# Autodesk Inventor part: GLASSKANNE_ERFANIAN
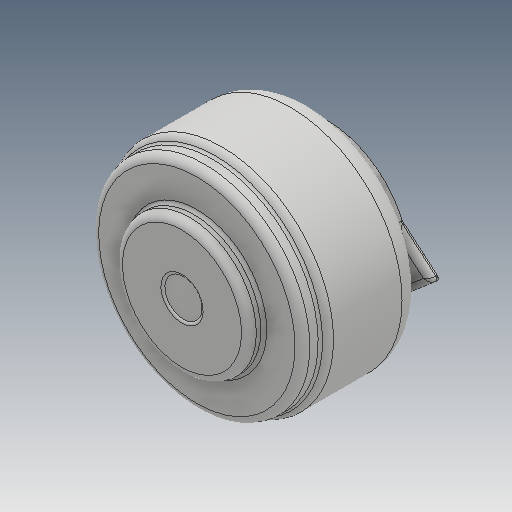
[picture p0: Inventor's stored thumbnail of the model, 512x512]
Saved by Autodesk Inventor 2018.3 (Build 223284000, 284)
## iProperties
Created: 2019-01
Part Number: GLASSKANNE_ERFANIAN
Material: Generisch
Document SubType Name: Modeling
Designer: zand
Density: 1 g/cm^3
Appearance: Vorgabe
Mass: 310.714 g
Surface Area: 1163.89 cm^2
Volume: 310.714 cm^3
Author: zand
Revision Number: 19LAST_VERSION
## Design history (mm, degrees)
feature "Basis1"
node "Volumenkörper1"
